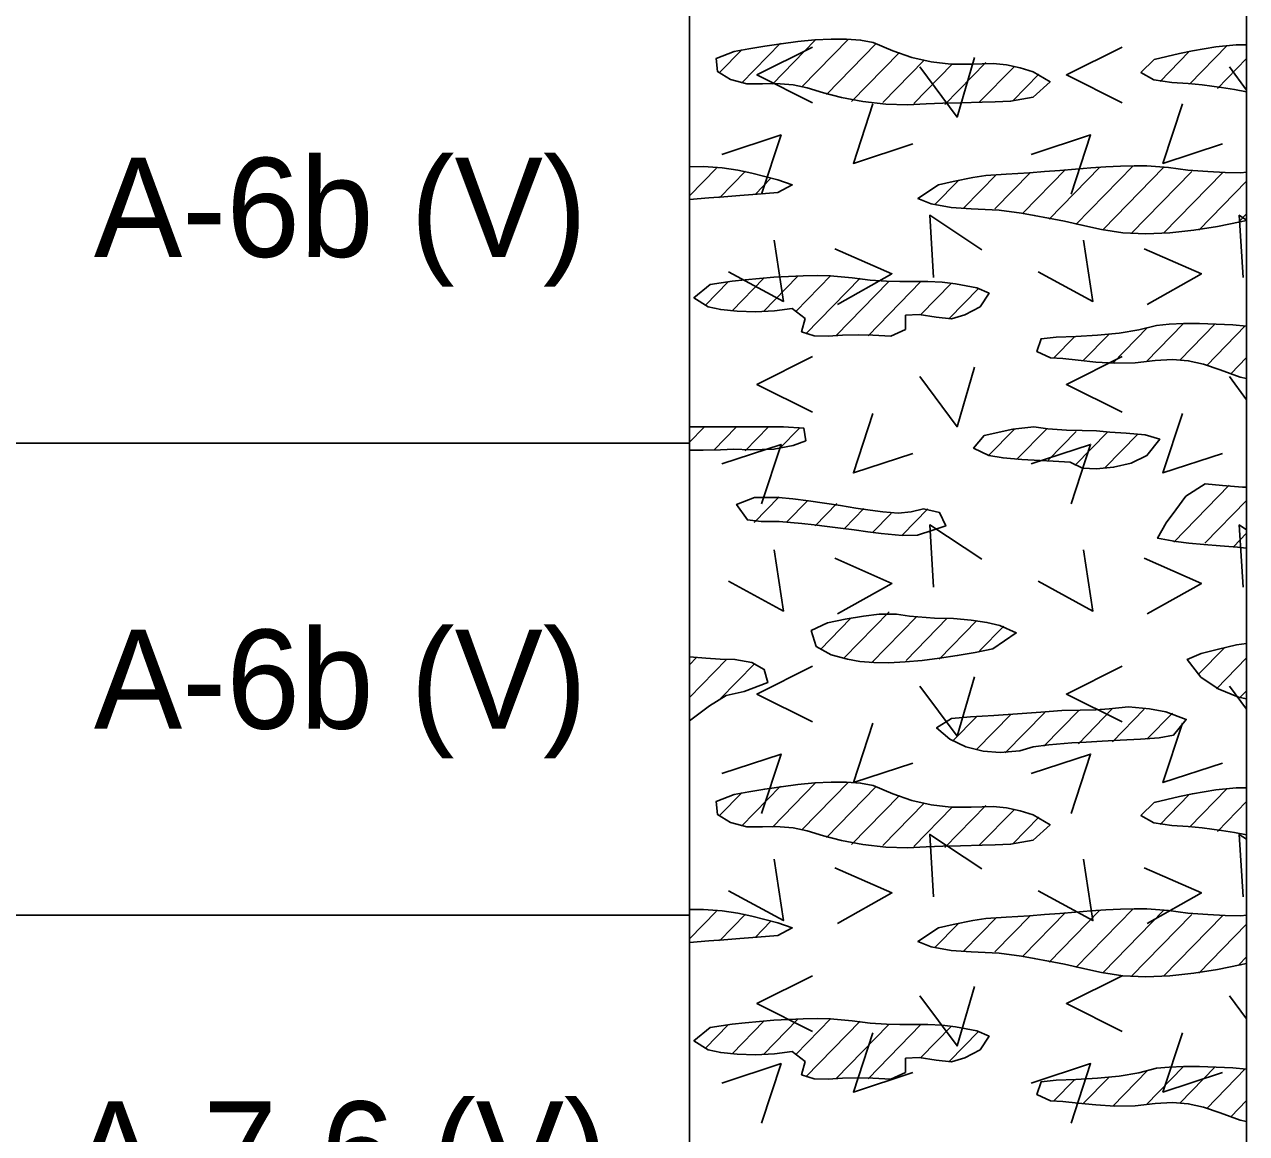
# Model space of a CAD drawing. Extents: x 0 to 0.833, y -0.32 to 0.608.
# Drawn here: x 0.7511 to 0.8333, y 0.3663 to 0.4409 of the extents above; entities that cross this region are included whole.
import ezdxf

# ---------------------------------------------------------------- set-up
doc = ezdxf.new("R2010")
doc.units = 0

msp = doc.modelspace()

# ---------------------------------------------------------------- linework, layer by layer
for points in [[(0, -0.320042), (0.833332, -0.320042), (0.833332, 0.608332), (0, 0.608332)], [(0.798854, 0.439113), (0.797634, 0.438652), (0.797728, 0.437756), (0.798587, 0.437233), (0.799696, 0.436937), (0.800742, 0.436947), (0.801652, 0.436961), (0.802809, 0.436877), (0.803766, 0.43667), (0.804856, 0.43632), (0.80606, 0.436024), (0.807509, 0.43575), (0.809046, 0.435564), (0.810517, 0.435533), (0.811769, 0.435591), (0.812889, 0.435631), (0.814075, 0.435666), (0.815527, 0.435707), (0.816416, 0.435733), (0.817445, 0.435764), (0.818967, 0.436038), (0.820111, 0.437074), (0.818963, 0.437743), (0.818099, 0.43801), (0.817169, 0.438206), (0.816265, 0.438311), (0.814793, 0.438253), (0.813435, 0.438256), (0.812104, 0.438406), (0.810802, 0.438708), (0.809527, 0.439168), (0.808198, 0.439718), (0.807356, 0.439878), (0.806403, 0.439952), (0.805364, 0.439953), (0.804267, 0.439892), (0.803138, 0.439784), (0.802006, 0.439639), (0.800896, 0.439471), (0.799837, 0.439291)], [(0.832629, 0.439559), (0.831261, 0.439422), (0.829688, 0.439156), (0.828826, 0.438983), (0.82712, 0.438572), (0.826226, 0.437703), (0.827084, 0.437212), (0.828308, 0.437025), (0.829408, 0.43696), (0.830335, 0.436871), (0.831655, 0.436688), (0.832526, 0.436546), (0.833332, 0.436404), (0.833332, 0.439552)], [(0.795832, 0.429156), (0.797147, 0.429266), (0.798141, 0.429339), (0.799224, 0.429417), (0.800394, 0.429502), (0.80179, 0.429624), (0.802748, 0.430138), (0.801793, 0.43048), (0.800911, 0.430694), (0.800027, 0.430915), (0.79909, 0.431121), (0.798029, 0.431287), (0.79677, 0.431382), (0.795832, 0.431362)], [(0.828162, 0.426908), (0.82978, 0.427078), (0.831374, 0.42733), (0.832902, 0.427641), (0.833332, 0.427746), (0.833332, 0.430986), (0.832951, 0.430953), (0.831885, 0.430975), (0.830714, 0.431028), (0.829383, 0.43113), (0.828069, 0.431299), (0.826619, 0.431418), (0.825765, 0.431421), (0.824843, 0.431393), (0.823868, 0.431343), (0.822856, 0.431274), (0.82182, 0.431195), (0.820774, 0.431111), (0.819735, 0.431028), (0.818715, 0.430953), (0.817148, 0.430858), (0.815785, 0.430765), (0.814914, 0.430632), (0.813574, 0.430357), (0.812595, 0.430144), (0.811206, 0.429226), (0.812105, 0.428864), (0.813452, 0.428618), (0.814789, 0.428528), (0.816678, 0.428425), (0.818181, 0.428225), (0.819046, 0.428079), (0.820004, 0.4279), (0.821067, 0.427685), (0.82225, 0.427434), (0.823565, 0.427142), (0.825013, 0.426916), (0.826559, 0.426847)], [(0.797084, 0.421927), (0.797938, 0.421749), (0.799042, 0.421637), (0.800285, 0.421603), (0.801555, 0.421657), (0.802742, 0.421811), (0.803614, 0.42115), (0.803377, 0.420253), (0.804221, 0.419982), (0.805167, 0.419964), (0.806129, 0.420019), (0.807202, 0.420051), (0.808182, 0.420019), (0.809387, 0.419946), (0.81037, 0.420412), (0.81038, 0.421359), (0.811296, 0.421421), (0.812442, 0.421234), (0.813463, 0.421128), (0.814379, 0.421384), (0.815394, 0.421926), (0.816006, 0.422839), (0.81517, 0.423212), (0.813738, 0.423488), (0.812849, 0.423581), (0.811872, 0.423639), (0.810001, 0.423641), (0.809104, 0.423659), (0.808002, 0.423733), (0.806784, 0.42389), (0.805305, 0.42402), (0.804427, 0.424033), (0.803488, 0.424017), (0.802511, 0.423977), (0.801521, 0.423915), (0.80054, 0.423837), (0.799593, 0.423746), (0.798702, 0.423647), (0.797221, 0.423423), (0.796138, 0.422546)], [(0.832407, 0.420708), (0.831293, 0.420772), (0.830172, 0.420809), (0.829096, 0.420811), (0.828115, 0.420772), (0.827281, 0.420684), (0.826083, 0.420385), (0.824762, 0.420159), (0.823296, 0.420022), (0.821831, 0.41994), (0.820509, 0.41988), (0.819505, 0.419782), (0.819224, 0.418917), (0.820125, 0.418498), (0.820967, 0.418447), (0.821997, 0.418347), (0.823181, 0.418217), (0.824476, 0.418129), (0.825838, 0.418154), (0.82719, 0.418318), (0.828356, 0.418385), (0.829402, 0.418304), (0.830435, 0.418071), (0.831559, 0.41768), (0.832909, 0.41719), (0.833332, 0.417114), (0.833332, 0.420633)], [(0.795832, 0.412295), (0.796757, 0.412285), (0.797925, 0.412304), (0.798816, 0.412343), (0.799915, 0.4123), (0.801515, 0.412344), (0.802823, 0.4126), (0.803666, 0.41292), (0.80354, 0.413759), (0.802165, 0.413844), (0.795832, 0.413844)], [(0.818216, 0.41165), (0.819444, 0.411591), (0.820325, 0.411551), (0.821453, 0.411483), (0.822286, 0.411069), (0.82324, 0.411025), (0.824378, 0.41113), (0.825554, 0.411418), (0.826624, 0.411923), (0.82749, 0.41302), (0.826513, 0.413323), (0.825239, 0.413424), (0.82413, 0.413488), (0.823236, 0.413594), (0.822257, 0.413613), (0.821211, 0.413637), (0.819948, 0.413728), (0.819024, 0.413844), (0.817611, 0.413704), (0.815663, 0.413261), (0.814958, 0.412422), (0.815983, 0.411933), (0.816947, 0.411758)], [(0.833053, 0.409796), (0.831709, 0.409908), (0.830539, 0.410009), (0.829246, 0.409189), (0.828567, 0.408275), (0.827924, 0.407388), (0.827345, 0.406361), (0.828579, 0.406136), (0.829451, 0.406035), (0.830451, 0.405938), (0.831549, 0.405843), (0.832716, 0.405746), (0.833332, 0.405695), (0.833332, 0.409787)], [(0.800664, 0.407493), (0.801881, 0.407486), (0.803392, 0.407358), (0.804229, 0.407262), (0.805103, 0.407152), (0.806004, 0.407034), (0.806919, 0.406913), (0.807838, 0.406794), (0.808747, 0.406684), (0.810142, 0.406543), (0.811186, 0.406555), (0.812223, 0.4069), (0.81308, 0.407185), (0.812673, 0.408087), (0.811597, 0.408334), (0.810749, 0.408136), (0.809892, 0.408053), (0.808847, 0.408134), (0.807995, 0.408245), (0.807033, 0.408389), (0.805997, 0.408552), (0.804922, 0.40872), (0.803843, 0.408877), (0.802797, 0.409009), (0.801817, 0.409101), (0.800202, 0.409109), (0.799007, 0.408637), (0.79974, 0.407594)], [(0.812326, 0.400987), (0.810635, 0.401106), (0.809773, 0.40124), (0.808601, 0.401247), (0.807553, 0.401103), (0.806321, 0.400904), (0.805133, 0.40066), (0.804031, 0.400139), (0.804359, 0.399079), (0.805363, 0.398512), (0.806466, 0.398214), (0.807303, 0.398063), (0.80824, 0.397987), (0.80926, 0.397978), (0.810349, 0.398029), (0.811489, 0.398131), (0.812666, 0.398278), (0.813863, 0.398462), (0.815063, 0.398675), (0.816252, 0.398909), (0.81783, 0.39999), (0.816735, 0.400489), (0.815852, 0.400691), (0.814797, 0.400849), (0.813609, 0.400951)], [(0.832654, 0.399175), (0.831362, 0.398866), (0.830275, 0.398591), (0.829339, 0.398197), (0.830265, 0.396997), (0.831418, 0.396234), (0.832792, 0.395656), (0.833332, 0.395557), (0.833332, 0.399265)], [(0.795832, 0.394079), (0.79719, 0.395069), (0.798312, 0.39577), (0.799509, 0.396042), (0.801112, 0.396643), (0.800861, 0.397527), (0.800021, 0.398003), (0.798893, 0.398197), (0.797908, 0.398227), (0.796943, 0.398284), (0.795832, 0.398366)], [(0.825375, 0.395022), (0.824078, 0.394872), (0.823187, 0.394815), (0.822142, 0.394791), (0.820907, 0.394754), (0.819474, 0.394661), (0.817918, 0.394541), (0.816318, 0.394421), (0.814751, 0.394329), (0.813476, 0.394228), (0.812472, 0.393588), (0.813366, 0.392828), (0.814436, 0.392323), (0.815612, 0.392035), (0.816749, 0.39193), (0.818067, 0.392042), (0.818959, 0.392318), (0.820031, 0.392462), (0.821573, 0.392584), (0.82253, 0.392642), (0.823615, 0.3927), (0.824832, 0.392762), (0.826183, 0.392828), (0.827451, 0.392936), (0.828416, 0.393111), (0.829268, 0.394166), (0.827909, 0.394683), (0.826788, 0.394882)], [(0.798854, 0.389113), (0.797634, 0.388652), (0.797728, 0.387756), (0.798587, 0.387233), (0.799696, 0.386937), (0.800742, 0.386947), (0.801652, 0.386961), (0.802809, 0.386878), (0.803766, 0.38667), (0.804856, 0.386321), (0.80606, 0.386024), (0.807509, 0.38575), (0.809046, 0.385564), (0.810517, 0.385533), (0.811769, 0.385591), (0.812889, 0.385631), (0.814075, 0.385667), (0.815527, 0.385707), (0.816416, 0.385733), (0.817445, 0.385764), (0.818967, 0.386038), (0.820111, 0.387074), (0.818963, 0.387743), (0.818099, 0.38801), (0.817169, 0.388207), (0.816265, 0.388311), (0.814793, 0.388253), (0.813435, 0.388256), (0.812104, 0.388406), (0.810802, 0.388708), (0.809527, 0.389168), (0.808198, 0.389718), (0.807356, 0.389878), (0.806403, 0.389952), (0.805364, 0.389953), (0.804267, 0.389893), (0.803138, 0.389784), (0.802006, 0.389639), (0.800896, 0.389471), (0.799837, 0.389291)], [(0.832629, 0.389559), (0.831261, 0.389422), (0.829688, 0.389157), (0.828826, 0.388983), (0.82712, 0.388572), (0.826226, 0.387704), (0.827084, 0.387212), (0.828308, 0.387025), (0.829408, 0.38696), (0.830335, 0.386871), (0.831655, 0.386688), (0.832526, 0.386546), (0.833332, 0.386404), (0.833332, 0.389552)], [(0.795832, 0.379156), (0.797147, 0.379267), (0.798141, 0.37934), (0.799224, 0.379417), (0.800394, 0.379502), (0.80179, 0.379624), (0.802748, 0.380139), (0.801793, 0.38048), (0.800911, 0.380694), (0.800027, 0.380915), (0.79909, 0.381122), (0.798029, 0.381287), (0.79677, 0.381383), (0.795832, 0.381362)], [(0.828162, 0.376908), (0.82978, 0.377078), (0.831374, 0.37733), (0.832902, 0.377641), (0.833332, 0.377746), (0.833332, 0.380986), (0.832951, 0.380953), (0.831885, 0.380975), (0.830714, 0.381028), (0.829383, 0.38113), (0.828069, 0.381299), (0.826619, 0.381418), (0.825765, 0.381421), (0.824843, 0.381394), (0.823868, 0.381343), (0.822856, 0.381274), (0.82182, 0.381195), (0.820774, 0.381111), (0.819735, 0.381028), (0.818715, 0.380953), (0.817148, 0.380858), (0.815785, 0.380765), (0.814914, 0.380632), (0.813574, 0.380357), (0.812595, 0.380145), (0.811206, 0.379226), (0.812105, 0.378864), (0.813452, 0.378618), (0.814789, 0.378528), (0.816678, 0.378425), (0.818181, 0.378225), (0.819046, 0.378079), (0.820004, 0.3779), (0.821067, 0.377685), (0.82225, 0.377434), (0.823565, 0.377142), (0.825013, 0.376917), (0.826559, 0.376847)], [(0.797084, 0.371927), (0.797938, 0.371749), (0.799042, 0.371637), (0.800285, 0.371603), (0.801555, 0.371657), (0.802742, 0.371812), (0.803614, 0.37115), (0.803377, 0.370253), (0.804221, 0.369982), (0.805167, 0.369964), (0.806129, 0.370019), (0.807202, 0.370051), (0.808182, 0.370019), (0.809387, 0.369946), (0.81037, 0.370412), (0.81038, 0.371359), (0.811296, 0.371421), (0.812442, 0.371234), (0.813463, 0.371128), (0.814379, 0.371384), (0.815394, 0.371926), (0.816006, 0.372839), (0.81517, 0.373212), (0.813738, 0.373488), (0.812849, 0.373581), (0.811872, 0.373639), (0.810001, 0.373641), (0.809104, 0.373659), (0.808002, 0.373733), (0.806784, 0.37389), (0.805305, 0.37402), (0.804427, 0.374034), (0.803488, 0.374018), (0.802511, 0.373977), (0.801521, 0.373915), (0.80054, 0.373837), (0.799593, 0.373746), (0.798702, 0.373647), (0.797221, 0.373424), (0.796138, 0.372546)], [(0.832407, 0.370708), (0.831293, 0.370772), (0.830172, 0.370809), (0.829096, 0.370812), (0.828115, 0.370772), (0.827281, 0.370685), (0.826083, 0.370385), (0.824762, 0.370159), (0.823296, 0.370022), (0.821831, 0.36994), (0.820509, 0.36988), (0.819505, 0.369782), (0.819224, 0.368917), (0.820125, 0.368499), (0.820967, 0.368447), (0.821997, 0.368347), (0.823181, 0.368217), (0.824476, 0.368129), (0.825838, 0.368154), (0.82719, 0.368318), (0.828356, 0.368385), (0.829402, 0.368304), (0.830435, 0.368071), (0.831559, 0.36768), (0.832909, 0.36719), (0.833332, 0.367114), (0.833332, 0.370633)]]:
    msp.add_lwpolyline(points, close=True)
for points in [[(0.795832, 0.554166), (0.795832, -0.275166)], [(0.833332, -0.275166), (0.833332, 0.503766)], [(0.799328, 0.436987), (0.801951, 0.439675)], [(0.804125, 0.439414), (0.800375, 0.437539), (0.804125, 0.435664)], [(0.801419, 0.436916), (0.804299, 0.439868)], [(0.806532, 0.439944), (0.803395, 0.436729)], [(0.805059, 0.436221), (0.808397, 0.439641)], [(0.824958, 0.439414), (0.821208, 0.437539), (0.824958, 0.435664)], [(0.832025, 0.439508), (0.829489, 0.436908)], [(0.799375, 0.439249), (0.797863, 0.437699)], [(0.809973, 0.439044), (0.806747, 0.435738)], [(0.811636, 0.438536), (0.808841, 0.435672)], [(0.811342, 0.438073), (0.813842, 0.434698), (0.815029, 0.438698)], [(0.827512, 0.437095), (0.82945, 0.439081)], [(0.831379, 0.436633), (0.833332, 0.438634)], [(0.813527, 0.43826), (0.810936, 0.435606)], [(0.813032, 0.43554), (0.815789, 0.438366)], [(0.815342, 0.435694), (0.817681, 0.438091)], [(0.832175, 0.438073), (0.833332, 0.436511)], [(0.817605, 0.4358), (0.819344, 0.437583)], [(0.833327, 0.436417), (0.833332, 0.436422)], [(0.808181, 0.435582), (0.806868, 0.431582), (0.810868, 0.432895)], [(0.829014, 0.435582), (0.827702, 0.431582), (0.831702, 0.432895)], [(0.800689, 0.429502), (0.802002, 0.433502), (0.798002, 0.432189)], [(0.821523, 0.429502), (0.822835, 0.433502), (0.818835, 0.432189)], [(0.797655, 0.431269), (0.795832, 0.429401)], [(0.799604, 0.431053), (0.797864, 0.429271)], [(0.818285, 0.428249), (0.821137, 0.431171)], [(0.820035, 0.427829), (0.823455, 0.431333)], [(0.825691, 0.431411), (0.82184, 0.427466)], [(0.827752, 0.43131), (0.823702, 0.427162)], [(0.801295, 0.430574), (0.800268, 0.429522)], [(0.813923, 0.430417), (0.812354, 0.42881)], [(0.814303, 0.428594), (0.816499, 0.430843)], [(0.816395, 0.428524), (0.818789, 0.430978)], [(0.829644, 0.431036), (0.825565, 0.426858)], [(0.831735, 0.430967), (0.827743, 0.426876)], [(0.833332, 0.430389), (0.830118, 0.427097)], [(0.815512, 0.425776), (0.812012, 0.428088), (0.812262, 0.423901)], [(0.832808, 0.427641), (0.833332, 0.428177)], [(0.833332, 0.427767), (0.832845, 0.428088), (0.833095, 0.423901)], [(0.798466, 0.424293), (0.802154, 0.422293), (0.801529, 0.426418)], [(0.8193, 0.424293), (0.822987, 0.422293), (0.822362, 0.426418)], [(0.805617, 0.425839), (0.809456, 0.424155), (0.805806, 0.422093)], [(0.82645, 0.425839), (0.83029, 0.424155), (0.826639, 0.422093)], [(0.79871, 0.42167), (0.800849, 0.423861)], [(0.800827, 0.421626), (0.803111, 0.423966)], [(0.805344, 0.424041), (0.802987, 0.421626)], [(0.80367, 0.420114), (0.807321, 0.423854)], [(0.798444, 0.42361), (0.796912, 0.42204)], [(0.805714, 0.419995), (0.809241, 0.423609)], [(0.811418, 0.423627), (0.807854, 0.419974)], [(0.811407, 0.421403), (0.81348, 0.423528)], [(0.815282, 0.423161), (0.813313, 0.421144)], [(0.824327, 0.418139), (0.82666, 0.420529)], [(0.829094, 0.420811), (0.826565, 0.418219)], [(0.828848, 0.418347), (0.831218, 0.420775)], [(0.833245, 0.42064), (0.830651, 0.417981)], [(0.820346, 0.418485), (0.821763, 0.419937)], [(0.822335, 0.41831), (0.824076, 0.420095)], [(0.804125, 0.418581), (0.800375, 0.416706), (0.804125, 0.414831)], [(0.824958, 0.418581), (0.821208, 0.416706), (0.824958, 0.414831)], [(0.833332, 0.418515), (0.832267, 0.417423)], [(0.811342, 0.41724), (0.813842, 0.413865), (0.815029, 0.417865)], [(0.832175, 0.41724), (0.833332, 0.415678)], [(0.808181, 0.414749), (0.806868, 0.410749), (0.810868, 0.412061)], [(0.829014, 0.414749), (0.827702, 0.410749), (0.831702, 0.412061)], [(0.795832, 0.412814), (0.796808, 0.413814)], [(0.798985, 0.413832), (0.797473, 0.412283)], [(0.801161, 0.413849), (0.799593, 0.412242)], [(0.803281, 0.413809), (0.801883, 0.412377)], [(0.817701, 0.413708), (0.815961, 0.411924)], [(0.819878, 0.413725), (0.817852, 0.411649)], [(0.821854, 0.413537), (0.819972, 0.411608)], [(0.824002, 0.413525), (0.821778, 0.411246)], [(0.826007, 0.413367), (0.823783, 0.411088)], [(0.749999, 0.412749), (0.795832, 0.412749)], [(0.800689, 0.408669), (0.802002, 0.412669), (0.798002, 0.411356)], [(0.821523, 0.408669), (0.822835, 0.412669), (0.818835, 0.411356)], [(0.832167, 0.409922), (0.828441, 0.406104)], [(0.801877, 0.409148), (0.800195, 0.407425)], [(0.803798, 0.408904), (0.80237, 0.407441)], [(0.833332, 0.408903), (0.830521, 0.406023)], [(0.805745, 0.408687), (0.804291, 0.407196)], [(0.80758, 0.408354), (0.806268, 0.407009)], [(0.809414, 0.408021), (0.808159, 0.406735)], [(0.811876, 0.408331), (0.810165, 0.406577)], [(0.815512, 0.404943), (0.812012, 0.407255), (0.812262, 0.403068)], [(0.833332, 0.406934), (0.832845, 0.407255), (0.833095, 0.403068)], [(0.833332, 0.40669), (0.832451, 0.405787)], [(0.798466, 0.40346), (0.802154, 0.40146), (0.801529, 0.405585)], [(0.8193, 0.40346), (0.822987, 0.40146), (0.822362, 0.405585)], [(0.805617, 0.405005), (0.809456, 0.403322), (0.805806, 0.40126)], [(0.82645, 0.405005), (0.83029, 0.403322), (0.826639, 0.40126)], [(0.804649, 0.398871), (0.806674, 0.400946)], [(0.806256, 0.398304), (0.809278, 0.401401)], [(0.80809, 0.397971), (0.811113, 0.401068)], [(0.810409, 0.398135), (0.813175, 0.400969)], [(0.812643, 0.398211), (0.815181, 0.400811)], [(0.815361, 0.398783), (0.816987, 0.400448)], [(0.830098, 0.397208), (0.831838, 0.398991)], [(0.796303, 0.398325), (0.795832, 0.397841)], [(0.798338, 0.398197), (0.795832, 0.395629)], [(0.831305, 0.396234), (0.833332, 0.39831)], [(0.797862, 0.395497), (0.800229, 0.397922)], [(0.804125, 0.397747), (0.800375, 0.395872), (0.804125, 0.393997)], [(0.824958, 0.397747), (0.821208, 0.395872), (0.824958, 0.393997)], [(0.811342, 0.396406), (0.813842, 0.393031), (0.815029, 0.397031)], [(0.832175, 0.396406), (0.833332, 0.394845)], [(0.832854, 0.395608), (0.833332, 0.396097)], [(0.822015, 0.392532), (0.824297, 0.39487)], [(0.824306, 0.392667), (0.826445, 0.394859)], [(0.815192, 0.394392), (0.813538, 0.392697)], [(0.815145, 0.392131), (0.817482, 0.394526)], [(0.817092, 0.391913), (0.819744, 0.39463)], [(0.819696, 0.392368), (0.822034, 0.394765)], [(0.826625, 0.392831), (0.828336, 0.394584)], [(0.808181, 0.393916), (0.806868, 0.389916), (0.810868, 0.391228)], [(0.829014, 0.393916), (0.827702, 0.389916), (0.831702, 0.391228)], [(0.800689, 0.387835), (0.802002, 0.391835), (0.798002, 0.390523)], [(0.821523, 0.387835), (0.822835, 0.391835), (0.818835, 0.390523)], [(0.806532, 0.389944), (0.803395, 0.386729)], [(0.799375, 0.389249), (0.797863, 0.387699)], [(0.799328, 0.386987), (0.801951, 0.389675)], [(0.801419, 0.386916), (0.804299, 0.389868)], [(0.805059, 0.386221), (0.808397, 0.389641)], [(0.832025, 0.389508), (0.829489, 0.386908)], [(0.809973, 0.389044), (0.806747, 0.385738)], [(0.811636, 0.388536), (0.808841, 0.385672)], [(0.813032, 0.38554), (0.815789, 0.388366)], [(0.827512, 0.387096), (0.82945, 0.389081)], [(0.831379, 0.386633), (0.833332, 0.388634)], [(0.813527, 0.38826), (0.810936, 0.385606)], [(0.815342, 0.385694), (0.817681, 0.388091)], [(0.817605, 0.3858), (0.819344, 0.387583)], [(0.815512, 0.384109), (0.812012, 0.386422), (0.812262, 0.382234)], [(0.833332, 0.3861), (0.832845, 0.386422), (0.833095, 0.382234)], [(0.833327, 0.386417), (0.833332, 0.386422)], [(0.798466, 0.382627), (0.802154, 0.380627), (0.801529, 0.384752)], [(0.805617, 0.384172), (0.809456, 0.382489), (0.805806, 0.380427)], [(0.8193, 0.382627), (0.822987, 0.380627), (0.822362, 0.384752)], [(0.82645, 0.384172), (0.83029, 0.382489), (0.826639, 0.380427)], [(0.749999, 0.380999), (0.795832, 0.380999)], [(0.797655, 0.38127), (0.795832, 0.379401)], [(0.799604, 0.381054), (0.797864, 0.379271)], [(0.816395, 0.378524), (0.818789, 0.380979)], [(0.818285, 0.378249), (0.821137, 0.381171)], [(0.820035, 0.377829), (0.823455, 0.381334)], [(0.825691, 0.381411), (0.82184, 0.377466)], [(0.827752, 0.381311), (0.823702, 0.377162)], [(0.829644, 0.381036), (0.825565, 0.376858)], [(0.831735, 0.380967), (0.827743, 0.376877)], [(0.801295, 0.380574), (0.800268, 0.379522)], [(0.813923, 0.380417), (0.812354, 0.37881)], [(0.814303, 0.378594), (0.816499, 0.380843)], [(0.833332, 0.380389), (0.830118, 0.377097)], [(0.832808, 0.377641), (0.833332, 0.378177)], [(0.804125, 0.376914), (0.800375, 0.375039), (0.804125, 0.373164)], [(0.824958, 0.376914), (0.821208, 0.375039), (0.824958, 0.373164)], [(0.811342, 0.375573), (0.813842, 0.372198), (0.815029, 0.376198)], [(0.832175, 0.375573), (0.833332, 0.374012)], [(0.798444, 0.37361), (0.796912, 0.37204)], [(0.79871, 0.37167), (0.800849, 0.373861)], [(0.800827, 0.371626), (0.803111, 0.373966)], [(0.805344, 0.374041), (0.802987, 0.371626)], [(0.80367, 0.370114), (0.807321, 0.373854)], [(0.805714, 0.369996), (0.809241, 0.37361)], [(0.811418, 0.373627), (0.807854, 0.369974)], [(0.811407, 0.371403), (0.81348, 0.373528)], [(0.808181, 0.373082), (0.806868, 0.369082), (0.810868, 0.370395)], [(0.815282, 0.373162), (0.813313, 0.371144)], [(0.829014, 0.373082), (0.827702, 0.369082), (0.831702, 0.370395)], [(0.800689, 0.367002), (0.802002, 0.371002), (0.798002, 0.36969)], [(0.821523, 0.367002), (0.822835, 0.371002), (0.818835, 0.36969)], [(0.824327, 0.368139), (0.82666, 0.370529)], [(0.829094, 0.370811), (0.826565, 0.368219)], [(0.828848, 0.368347), (0.831218, 0.370775)], [(0.833245, 0.37064), (0.830651, 0.367981)], [(0.820346, 0.368485), (0.821763, 0.369937)], [(0.822335, 0.36831), (0.824076, 0.370095)], [(0.833332, 0.368515), (0.832267, 0.367423)]]:
    msp.add_lwpolyline(points)

# ---------------------------------------------------------------- texts
for s, p in [('A-6b (V)', (0.755748, 0.425291)), ('A-6b (V)', (0.755748, 0.393541)), ('A-7-6 (V)', (0.754198, 0.361791))]:
    msp.add_text(s, height=0.0066667).set_placement(p)

doc.saveas('drawing.dxf')
